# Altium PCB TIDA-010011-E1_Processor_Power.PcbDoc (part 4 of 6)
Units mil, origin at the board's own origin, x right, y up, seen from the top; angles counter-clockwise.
Board outline 4921.26 x 4921.26 mil, 4 copper layers (Top Layer, Gnd layer, Gnd/Pwr layer, Bottom Layer), stack 62.634 mil thick; 631 components, 254 nets, 1751 pads, 757 vias.
Unrouted connection lines stored in the file: 1.
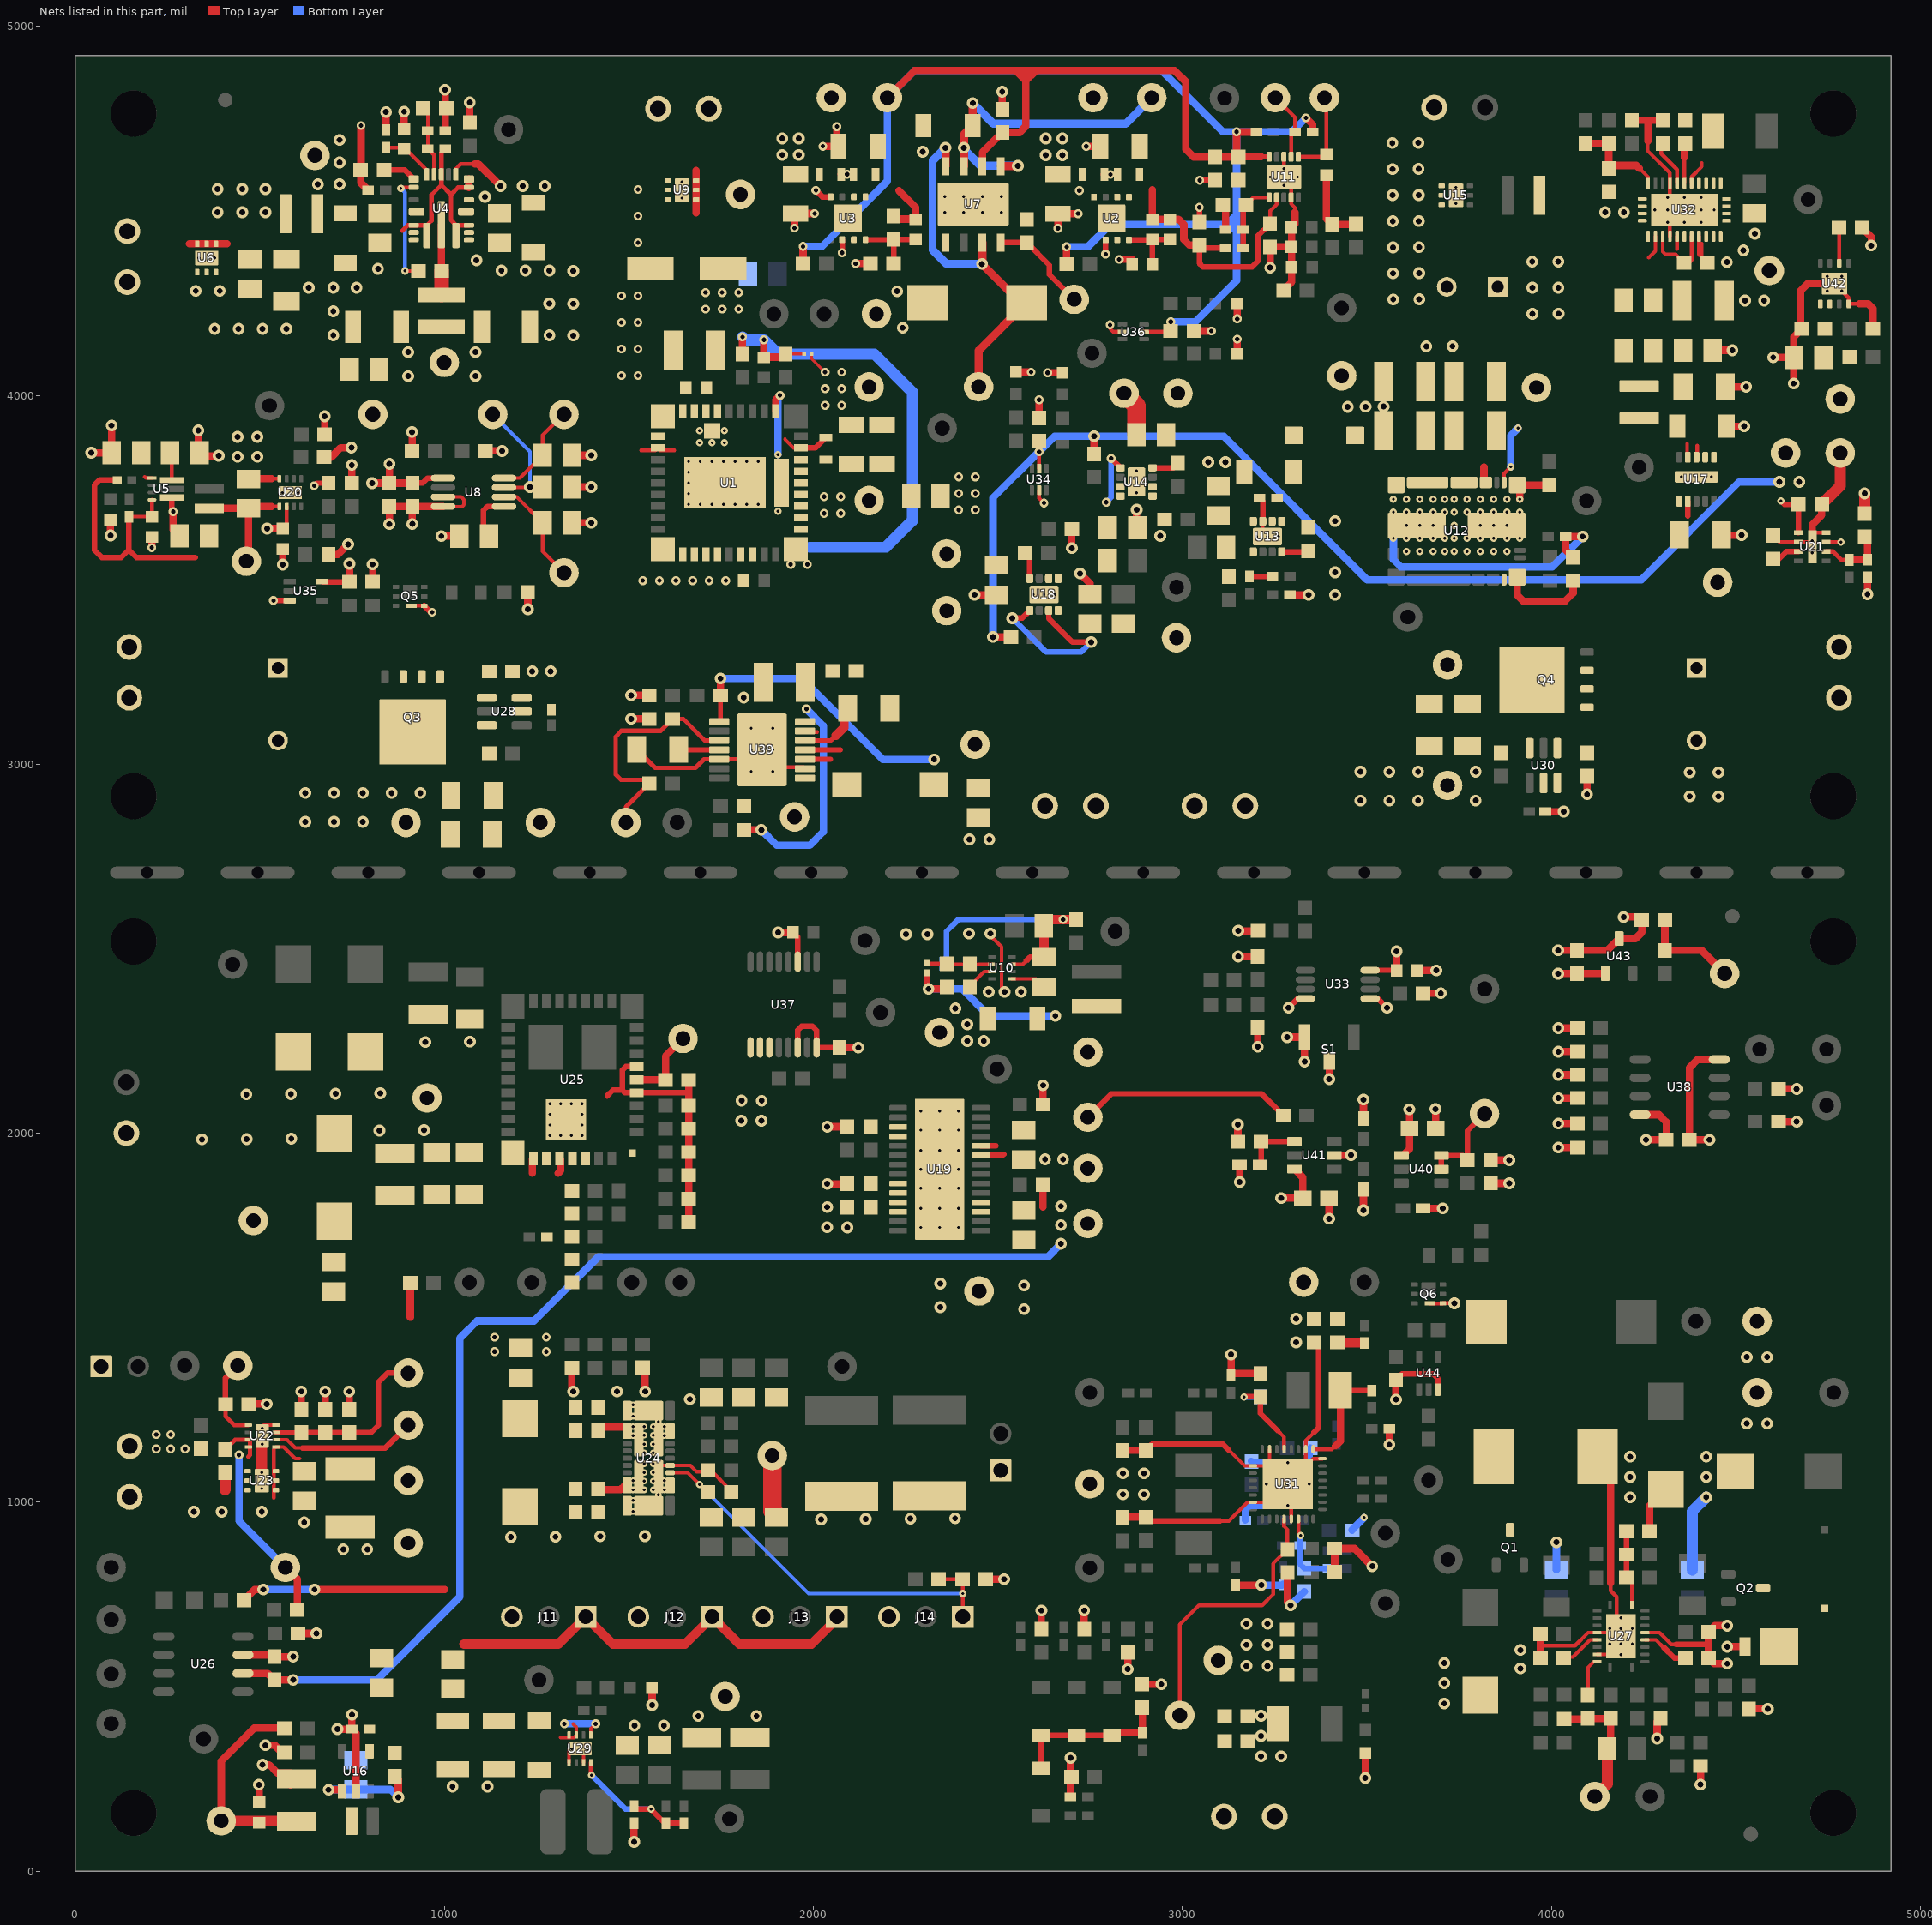
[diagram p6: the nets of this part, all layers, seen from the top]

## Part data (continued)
U41: "Low Quiescent Current, Programmable-Delay Supervisory Circuit, DBV0006A (SOT-6)", Alternate Manufacturer="Texas Instruments", Alternate PartNumber=TPS3808G01DBVT, Supplier Part Number 1=296-17188-1-ND
U42: library part CMP-0065176-3, "Low-Noise, High-Bandwidth PSRR, 1A Low-Dropout Linear Regulator, DRB0008A (VSON-8)", Alternate Manufacturer="Texas Instruments", Alternate PartNumber=TPS7A8001ADRBT, Supplier Part Number 1=296-27630-1-ND
U43: library part CMP-0013240-2, "TMP235DBZ, DBZ0003A (SOP-3)", Alternate Manufacturer="Texas Instruments"
U44: library part CMP-0051704-3, "Single Schmitt-Trigger Buffer, DCK0005A, LARGE T&R", F @ Nom Voltage(Max)(Mhz)=150, Generic Part Number=SN74LVC1G17, ICC @ Nom Voltage(Max)(mA)=0.01, Manufacturer="Texas Instruments", Operating Temperature Range(C)="-40 to 125,-40 to 85", Rating=Catalog, tpd @ Nom Voltage(Max)(ns)=11,6.5,5.5,5, Voltage(Nom)(V)=1.8,2.5,3.3,5
ZZ1: library part AssemblyNoteLabel, Alternate Manufacturer=-
ZZ2 ZZ3 ZZ4: library part AssemblyNote, Alternate Manufacturer=-

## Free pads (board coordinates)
  oval 200x32 hole 32 slot 200 at 0 deg unplated mask+10: 0(194,2706.42) 0(494,2706.42) 0(794,2706.42) 0(1094,2706.42) 0(1394,2706.42) 0(1694,2706.42) 0(1994,2706.42) 0(2294,2706.42) 0(2594,2706.42) 0(2894,2706.42) 0(3194,2706.42) 0(3494,2706.42) 0(3794,2706.42) 0(4094,2706.42) 0(4394,2706.42) 0(4694,2706.42)

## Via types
v1: diameter 32, hole 16, Top Layer to Bottom Layer, tented both sides, 400 vias
v2: diameter 19.68, hole 7.87, Top Layer to Bottom Layer, 176 vias
v3: diameter 24, hole 12, Top Layer to Bottom Layer, tented both sides, 112 vias
v4: diameter 20, hole 8, Top Layer to Bottom Layer, tented both sides, 35 vias
v5: diameter 17.72, hole 7.87, Top Layer to Bottom Layer, 30 vias
v6: diameter 19.68, hole 7.87, Top Layer to Bottom Layer, tented both sides, 4 vias

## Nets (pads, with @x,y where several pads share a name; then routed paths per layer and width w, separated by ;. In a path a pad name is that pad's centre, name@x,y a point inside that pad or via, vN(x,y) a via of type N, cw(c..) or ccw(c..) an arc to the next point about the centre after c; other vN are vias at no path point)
1.2V/1A: C183.1 C185.1 L18.2 R174.2 TP104.1 | length 470.8
  Top Layer w15: C183.1@2309,2435.01 2309,2394 v1(2312,2391)
  Top Layer w20: v1(2312,2391) 2355.5,2391 R174.2@2361,2396.5
  Bottom Layer w20: v1(2312,2391) 2403,2391 2476,2318 v1(2656,2318)
1.2V_CPM: C51.1 R25.2 TP13.1 U14.8 | length 74.2
  Top Layer w15: U14.8@2919,3803.5 2975.5,3803.5 R25.2@2988,3816
1.8V: C9.1 C10.1 C11.1 C42.1 C170.1 C174.2 R1.2 R22.2 TP6.1 U2.5 U7.5 U7.7 U11.2 | length 1675.7
  Top Layer w10: C170.1@3238,4465.5 3238,4500 3255.43,4517.43 U11.2@3255.43,4536.35
  Top Layer w15: C42.1@3046,4406.97 C42.1@3046,4406.5 ; R22.2@3117.49,4399.46 3053.04,4399.46 C42.1@3046,4406.5 ; C170.1@3238,4465.5 3204.1,4431.6 3204.1,4363.1 3189,4348 3056,4348 3046,4358 C42.1@3046,4406.5
  Top Layer w20: 2918.87,4556.87 R1.2@2918.87,4477.33 2918.93,4477.39 C9.1@2966.07,4477.39 2989.61,4477.39 3004,4463 3004,4422 3019.03,4406.97 C42.1@3046,4406.97
  Top Layer w22: U7.7@2408,4620.69 v1(2408,4671) 2408,4707.07 C174.2@2431.93,4731 v1(2431.93,4791.93) ; U7.5@2508,4620.69 2553.69,4620.69 v1@2554,4621
  Bottom Layer w22: v1@2408,4667 2453,4622 v1(2554,4622) ; v1(2431.93,4791.93) 2487.86,4736 2846.5,4736 TP6.1@2917.07,4806.57
1.8V_CPM: C59.1 R35.2 TP19.1 U18.8 | length 74.2
  Top Layer w15: R35.2@2574.24,3572.24 2586.74,3559.75 U18.8@2586.74,3503.24
3.3V: C14.1 C15.1 C16.1 C40.1 C41.1 C158.1 C175.1 R5.2 R21.2 R23.2 R139.2 R141.2 TP8.1 U3.5 U7.6 U11.10 U36.5 | length 5154.7
  Top Layer w12: U36.5@2896.13,4171.72 2965.76,4171.72 C158.1@2968.5,4174.46 v3(2968.5,4199.22) ; 3213.11,4646.58 U11.10@3235.75,4646.58
  Top Layer w20: R141.2@1972.01,4357.06 v3(1972.01,4403.49) ; TP8.1@2200.5,4806.56 2273.94,4880 2979,4880 3009,4850 3009,4667 3030.04,4645.96 C40.1@3089.12,4645.96 C41.1@3152.12,4645.96 ; R5.2@2217.5,4485.49 2225.44,4477.55 C14.1@2277.5,4477.55 2277.5,4508.99 2231.5,4554.99 ; U7.6@2458,4620.69 2458,4658.5 C175.1@2512,4712.5 2559.5,4712.5 2576,4729 2576,4880 ; 2552,4880 2552,4877 2576,4853 2600,4877 2600,4880 ; R139.2@2686.5,4356 v3(2686.5,4402.43) ; R21.2@3200.49,4713.46 3147.54,4713.46 v3(3147,4714) 3147,4651.08 C41.1@3152.12,4645.96 ; 3213.11,4646.58 3152.74,4646.58 C41.1@3152.12,4645.96 ; v3(3335,4752) 3352.74,4734.26 R23.2@3352.74,4713.46
  Bottom Layer w20: v3(1972.01,4403.49) 2023.49,4403.49 2200.5,4580.5 TP8.1@2200.5,4806.56 2273.94,4880 2944,4880 3110,4714 v3(3147,4714) ; v3(2686.5,4402.43) 2726.57,4402.43 2744.43,4402.43 2805,4463 3147,4463 ; v3(2968.5,4199.22) 3035.22,4199.22 3147,4311 3147,4463 ; 3124,4463 3124,4467 3147,4490 ; 3128,4463 3147,4444 ; v3(3335,4752) 3297,4714 v3(3147,4714) ; 3147,4463 3147,4490 ; 3147,4490 v3(3147,4714)
3.3V_H: C31.1 C32.1 C147.1 C157.1 R12.2 R13.2 R14.2 R15.2 R112.2 R114.1 R118.1 R135.2 R138.1 TP75.1 U8.1 U20.2 U20.8 U35.5 | length 989.6
  Top Layer w10: 531.34,3773.66 U20.8@552.76,3773.66 ; C147.1@562,3638.56 572.44,3649 U20.2@572.44,3698.86
  Top Layer w15: U35.5@669.29,3494.85 669.88,3494.26 C157.1@742.5,3494.26 ; C32.1@912.5,3762.25 C32.1@913.5,3762.25 ; C32.1@913,3761.76 C32.1@913.5,3762.25 ; U8.1@996.32,3775.65 954.65,3775.65 941.25,3762.25 C32.1@913.5,3762.25
  Top Layer w20: R118.1@463,3779.26 R118.1@469,3773.26 469.4,3773.66 531.34,3773.66 ; v1(519.56,3638.56) C147.1@562,3638.56 ; R112.2@675.5,3894 v1(675.5,3943.24) ; R138.1@686,3568.76 711.76,3568.76 v1(739,3596) ; C157.1@742.5,3494.26 v1(742.5,3543.15) ; R114.1@749,3761.76 v1(749,3811) ; v1(804.24,3761.76) C31.1@851,3761.76 ; v1(851,3814) C31.1@851,3761.76 ; R15.2@912.5,3849.26 v1(912.5,3900.5) ; C32.1@913,3761.76 C31.1@851,3761.76 ; R135.2@1225.5,3466.26 1226,3466.76 v1(1226,3420) ; R14.2@1346,3654.26 v1(1397.74,3654.26) ; R13.2@1346,3751.26 v1(1397.74,3751.26) ; R12.2@1346,3837.26 v1(1397.74,3837.26)
  other v1: 439,3833 493,3833 439,3887 493,3887
3.6I_1P8V: C143.1 R165.1 TP57.1 U19.23 U19.24 | length 684.1
  Top Layer w15: U19.23@2454.2,1940.39 2513.39,1940.39 2516,1943 ; U19.24@2454.2,1965.98 2494.98,1965.98 ; TP57.1@2744,2043 2808,2107 3214.51,2107 R165.1@3273.51,2048
3.6I_3P3V: C144.1 C148.1 C155.2 C160.2 C166.1 C168.2 C189.2 R20.1 R38.1 R127.1 R146.2 R147.2 R148.2 R149.2 R150.2 R160.2 R162.2 R163.2 R164.2 TP60.1 U19.17 U19.18 U26.2 U33.4 U33.8 U38.8 U40.4 U41.6 U43.1 | length 4518.3
  Top Layer w15: v1(3288,2340) 3312.92,2364.92 U33.4@3333.71,2364.92 ; U33.8@3508.9,2441.69 3580.36,2441.69 C155.2@3580.74,2441.31
  Top Layer w20: U26.2@454.09,535.48 521.31,535.48 C148.1@538.81,517.98 v1(589.98,517.98) ; 2622.5,1799.5 R38.1@2622.5,1860 ; R20.1@2622.5,2078 v1(2622.5,2129.5) ; v1(3155.44,1867.44) R164.2@3155.44,1914 ; v1(3268,1824) C168.2@3326.57,1824 3326.57,1879.9 U41.6@3303.87,1902.6 ; v1(3491,1791) R162.2@3491,1847.44 ; R163.2@3491,2039.56 v1(3491,2091.06) ; C155.2@3580.74,2441.31 v1(3580.74,2492.81) ; U40.4@3593.87,1939.4 3597.84,1939.4 3615.57,1957.13 C166.1@3615.57,2013 v1(3615.57,2064.5) ; R160.2@3652.56,1796 v1(3706,1796) ; R127.1@3652.8,2379.31 v1(3700.69,2379.31) ; v1(4018.5,2432.5) C189.2@4070,2432.5 4070.25,2432.76 U43.1@4146.6,2432.76 ; v1(4019,2026) R146.2@4070.5,2026 ; v1(4019,2095) R147.2@4070.5,2095 ; v1(4019,2285) R148.2@4070.5,2285 ; U38.8@4240.72,2050 4292,2050 4311.5,2030.5 C160.2@4311.5,1982 v1(4257,1982) ; R150.2@4615.5,2031 v1(4665,2031) ; R149.2@4615.5,2120 v1(4665,2120)
  Bottom Layer w20: v1(589.98,517.98) 816.98,517.98 1042,743 1042,1444 1089,1491 1243,1491 1417,1665 2636,1665 v1(2671,1700)
  other v1: 2671,1751 2671,1802
5I_3P3V: C63.1 C156.1 R29.2 R36.1 TP77.1 U21.3 U21.5 U34.5 | length 3189.4
  Top Layer w10: U34.5@2612,3801.13 v3(2612,3847.02) 2612,3871.5 2614,3873.5 C156.1@2612,3875.5 ; U21.3@4744.8,3602 v4(4785,3602)
  Top Layer w15: v4(4622,3714) 4631.8,3704.2 C63.1@4669.91,3704.2 4670,3704.11 U21.5@4670,3627.59
  Top Layer w20: v1(2487,3345) R36.1@2535.5,3345 ; R29.2@2761,3841 v1(2761,3889)
  Bottom Layer w20: v1(2487,3345) 2487,3722.02 v3(2612,3847.02) 2653.98,3889 v1(2761,3889) 3112,3889 3501,3500 4244,3500 4509,3765 v1(4618,3765)
  other v1: 4672,3765
5V: C4.1 C5.1 C6.1 R177.2 TP2.1 U1.13 U1.14 U1.15 U1.16 U1.17 U1.18 U1.22 U1.43 | length 210.6
  Top Layer w20: U1.22@1898,3956.57 1898,3988 v3(1909.67,3999.67)
  Bottom Layer w20: v2(1903.9,3839.44) 1903.9,3993.9 v3(1909.67,3999.67)
  other v2: 1903.9,3685.9
  other v3: 2029,3680 2074,3680 2029,3725 2074,3725
5V_EFUSE_OUT: C65.1 C66.1 J11.1 J12.1 J13.1 R56.1 R120.2 R180.2 R181.1 R182.2 TP23.1 U22.5 U23.4 U23.5 U23.6 | length 2036.6
  Top Layer w10: 537.39,1011.93 537.39,1143.19 537.25,1143.32 U22.5@543.4,1149.47 564.12,1149.47 595.59,1118 607,1118
  Top Layer w20: R120.2@456.5,734 485.5,763 v1(509,763) ; v1@648,761 v1(648,763) 1001,763 ; 907.5,1501.5 R56.1@907.5,1594
  Top Layer w25: 1053,615 1308.81,615 J11.1@1382.73,688.92 1456.65,615 1651.81,615 J12.1@1725.73,688.92 1799.65,615 1994.81,615 J13.1@2068.73,688.92
  Bottom Layer w20: v1(509,763) v1(648,763)
5V_H: C24.1 C25.1 C30.2 L2.2 R10.1 R176.2 RB1.2 RES1.1 TP35.1 | length 214.1
  Top Layer w20: RB1.2@841.74,4718.72 v1(841.74,4767.74) ; R10.1@1002.36,4717.1 v1@1002.36,4828 ; RES1.1@1068.74,4739.6 v1(1068.74,4793.74)
  other v1: 901.52,4052 1084,4052 901.52,4117 1084,4117 1002,4828
12VOUT: C48.1 C49.1 L5.2 R19.2 R32.2 TP15.1 U12.6 U12.7 U12.8@3635.52,3647.64 | length 724
  Top Layer w20: R32.2@4059.2,3560.09 4038.95,3580.34 R19.2@4038.95,3617.09 v1(4085.09,3617.09)
  Bottom Layer w20: v2(3572.25,3612.2) 3572.25,3554.75 3592,3535 4003,3535 v1(4085.09,3617.09)
  other v1: 3448.38,3968.62 3497,3969 3545.62,3969.38
  other v2: 3608.08,3612.2 3643.9,3612.2 3679.73,3612.2 3711.22,3612.2 3608.08,3647.64 3643.9,3647.64 3679.73,3647.64 3572.25,3683.07 3608.08,3683.07 3643.9,3683.07 3679.73,3683.07 3711.22,3683.07 3572.25,3718.5 3608.08,3718.5 3643.9,3718.5 3679.73,3718.5 3711.22,3718.5
24V_S: C45.1 C46.1 C47.1 L4.2 R166.2 R167.2 TP14.1 U12.2 U12.4 | length 206.5
  Top Layer w6: v4@3884,3800 v4(3890,3806)
  Top Layer w10: U12.2@3871.66,3763.98 3871.66,3787.66 v4@3884,3800
  Top Layer w20: 3817.5,3805.5 3817.5,3768.92 U12.4@3822.45,3763.98
  Bottom Layer w20: v4(3890,3806) 3890,3891 v4(3910,3911)
  other v1: 3949,4221 4019.62,4221.38 3948.62,4291.62 4019.24,4292 3948.24,4362.24 4018.86,4362.62
AGND: C111.2 NT1.1 R3.1 R4.1 R18.1 U1.1 U1.2 U1.3 U1.4 U1.5 U1.7 U1.8 U1.11 U1.12 | length 1384.3
  Top Layer w8: R18.1@1924.42,4111.67 NT1.1@1974.67,4111.67
  Top Layer w20: C111.2@1808.01,4111.27 v3(1808.01,4158.32) ; v3(1866.01,4150.38) R4.1@1866.01,4103.33 1916.08,4103.33 R18.1@1924.01,4111.27
  Bottom Layer w30: v3(1808.01,4158.32) 1815.95,4150.38 v3(1866.01,4150.38) 1904.4,4112 2165,4112 2268,4009 2268,3660 2196,3588 1990,3588
  other v3: 1537.67,3497.67 1582.67,3497.67 1627.67,3497.67 1672.67,3497.67 1717.67,3497.67 1762.67,3497.67 1938.67,3541.67 1983.67,3541.67
DDR_VREF: C43.1 TP11.1 U11.6 | length 236.8
  Top Layer w10: U11.6@3314.49,4646.58 3388.61,4646.58 3390.12,4648.09 C43.1@3390.12,4652.02 3390.12,4801.2 TP11.1@3384.86,4806.46
DDR_VTT_EN: R23.1 TP76.1 U11.7 | length 186.4
  Top Layer w10: TP76.1@3267.29,4791.29 3305.49,4753.09 R23.1@3305.49,4713.46 3294.8,4702.77 U11.7@3294.8,4646.58
  Top Layer w12: TP76.1@3252.12,4806.46 TP76.1@3267.29,4791.29
DV/DT: C68.1 TP26.1 U22.1 | length 223.4
  Top Layer w12: C68.1@406.5,1266 406.5,1232.5 430.47,1208.53 U22.1@468.6,1208.53
  Top Layer w15: C68.1@406.5,1266 406.5,1336.5 TP26.1@440,1370
FLAG1: R12.1 TP72.1 U8.8 | length 266.6
  Top Layer w10: U8.8@1161.68,3775.65 1204.39,3775.65 R12.1@1266,3837.26 1266,3892 TP72.1@1324,3950
FLAG2: R13.1 TP73.1 U8.7 | length 343.7
  Top Layer w10: U8.7@1161.68,3750.06 1264.8,3750.06 R13.1@1266,3751.26
  Bottom Layer w10: TP73.1@1131,3948.26 1232,3847.26 v1(1232,3751.26)
FLAG3: R14.1 TP74.1 U8.6 | length 292.7
  Top Layer w10: U8.6@1161.68,3724.46 1195.8,3724.46 R14.1@1266,3654.26 1266,3577 TP74.1@1324,3519
FLT: TP25.1 U22.6 | length 393.5
  Top Layer w10: U22.6@543.4,1169.16 573.28,1169.16 595.43,1147 615.57,1147
  Top Layer w15: 615.57,1147 840,1147 TP25.1@902,1209
GND: C1.2 C2.2 C3.1 C4.2 C5.2 C6.2 C7.2 C8.2 C10.2 C11.2 C12.2 C13.2 C15.2 C16.2 C18.2 C19.2 C20.2 C21.2 C22.2 C23.2 C24.2 C25.2 C26.2 C27.2 C28.2 C29.2 C31.2 C32.2 C33.2 C34.2 C35.2 C36.2 C37.2 C38.2 C39.2 C40.2 C41.2 C42.2 C43.2 C44.2 C45.2 C46.2 C47.2 C48.2 C49.2 C50.2 C51.2 C52.2 C53.2 C54.2 C55.1 C56.2 C57.2 C58.2 C59.2 C60.2 C61.2 C62.2 C63.2 C64.2 C110.2 C127.2 C128.2 C129.2 C130.2 C139.2 C140.2 C141.2 C142.2 C147.2 C150.2 C151.2 C152.1 C153.2 C156.2 C157.2 C158.2 C161.2 C163.2 C164.1 C165.1 C170.2 C171.2 C172.2 C173.2 C174.1 C175.2 C176.2 C182.2 CVCC1.2 D3.2 D4.2 D6.2 D7.2 D10.2 D16.2 J1.2 J2.2 J3.2 J4.1 J18.2 J19.2 J20.1 NT1.2 Q5.4 Q5.7 R2.1 R6.1 R9.1 R11.1 R16.1 R17.2 R24.1 R30.1 R31.1 R33.1 R34.1 R37.1 R40.1 R116.1 R117.1 R123.1 R124.1 R155.1 R159.1 R169.1 TP4.1 TP7.1 TP9.1 TP17.1 TP21.1 TP43.1 TP69.1 TP78.1 TP93.1 TP96.1 TP101.1 U1.19 U1.29 U1.30 U1.31 U1.32 U1.33 U1.41 U2.3 U2.6 U2.9 U3.3 U3.6 U3.9 U4.5 U4.6 U4.7 U4.8 U4.10 U4.11 U4.12 U4.13 U4.16 U4.17 U4.20 U5.5 U6.1 U6.2 U6.3 U6.7@355.41,4372.39 U7.1 U7.9@2433,4517.35 U8.3 U8.4 U9.1 U9.2 U9.3 U9.7@1644.05,4556.26 U11.4 U11.8 U11.11@3275.12,4591.46 U12.1 U12.5 U12.14 U12.15 U12.18@3851.89,3647.64 U13.3 U13.9 U14.5 U14.6 U14.9 U15.1 U15.2 U15.3 U15.7@3741.71,4542.09 U17.1 U17.2 U17.11@4393.62,3779.11 U18.5 U18.6 U18.9 U20.9@582.28,3736.26 U21.4 U21.6 U21.9 U28.2 U28.3 U30.2 U30.3 U32.8 U32.12 U32.13 U32.14 U32.15 U32.16 U32.17 U32.19 U32.23 U32.24 U32.25 U32.26 U32.27 U32.28 U32.29 U32.30 U32.31 U34.2 U35.3 U36.2 U39.5 U39.8 U39.9 U39.15@1861,3039 U42.4 U42.9 | length 7675
  Top Layer w8: NT1.2@1994.67,4111.67 1994.67,4099.67 v3(2031.67,4062.67)
  Top Layer w10: Q5.7@910.74,3429.67 Q5.4@945.39,3429.67 ; U8.4@996.32,3698.87 997.2,3698 1048,3698 1053,3703 1053,3717 1045.54,3724.46 U8.3@996.32,3724.46 ; 1532.67,3850.67 1571.63,3850.67 U1.33@1578.12,3857.16 1584.77,3850.5 1623.5,3850.5 ; U39.15@1861,3039 1908.15,2991.85 1973.11,2991.85 U39.9@1977.14,2987.82 ; 1923.19,3880.67 1946.7,3857.16 U1.19@1965.91,3857.16 ; U34.2@2612,3742.87 2612,3721 v3(2625,3708) ; v3(2804,4191) 2804,4181 2812.2,4172.8 2836.79,4172.8 U36.2@2837.87,4171.72 ; U13.9@3217.94,3629.8 U13.3@3217.94,3658.34 ; U11.8@3275.12,4646.58 v2(3275.12,4614.1) U11.11@3275.12,4591.46 3294.8,4571.78 U11.4@3294.8,4536.35 3294.8,4519.2 3305,4509 3305,4496 ; 4261.6,4689 4261.6,4662.4 4321.54,4602.46 U32.8@4321.54,4574.69 4321.54,4542.21 v2(4360.91,4502.84) 4321.54,4463.47 U32.19@4321.54,4430.99 ; 4264,4373 4282.17,4391.17 U32.17@4282.17,4430.99 ; U32.23@4400.28,4430.99 4400.28,4381.95 C151.2@4408,4374.24 ; 4408,4411.22 C151.2@4408,4374.24 ; C151.2@4423.24,4359 C151.2@4408,4374.24 ; C62.2@4601.4,3619.7 4619.1,3602 U21.6@4670,3602 4704.06,3602 v2(4707.4,3605.35) ; U21.9@4707.4,3627.59 U21.4@4744.8,3627.59 ; U42.9@4767.55,4302.92 4805.94,4264.53 U42.4@4805.94,4247.8 4835.46,4247.8
  Top Layer w12: 886,4446 900.84,4460.84 U4.5@916.94,4460.84 952.16,4460.84 965,4473.68 965,4543.52 991.74,4570.26 ; U4.8@952.37,4433.28 U4.8@953,4432.65 ; R9.1@1002.36,4668.1 991.74,4657.48 U4.20@991.74,4598.64 991.74,4570.26 ; U4.10@1031.11,4433.28 U4.10@1031.11,4460.84 ; U4.13@1066.54,4460.84 U4.10@1031.11,4460.84 ; U4.16@1066.54,4563.2 1037.2,4563.2 1018,4544 ; C164.1@1520.91,3040 1571.03,2989.88 1680.37,2989.88 1703.89,3013.41 1704.41,3013.41 ; 1702.52,3011.52 1704.41,3013.41 ; U39.15@1861,3039 1835.41,3013.41 U39.5@1744.86,3013.41 1704.41,3013.41 ; 991.74,4570.26 1018,4544 ; 1018,4544 1018,4475 1031.11,4461.89 U4.10@1031.11,4460.84
  Top Layer w15: U5.5@260.72,3722.64 260.72,3688.48 v3(264.6,3684.6) ; v3(536.67,3443.67) U35.3@580.71,3443.67 ; v3(647,3755) 653.76,3761.76 R117.1@686,3761.76 ; Q5.4@945.39,3429.67 963,3412.06 964.94,3414 v3(967,3411.94) ; U1.19@1965.91,3857.16 2005.4,3857.16 C4.2@2034.01,3885.77 ; C42.2@3046,4465.46 C42.2@3046,4469.5 v3(3046,4509.61) ; v3(3047.03,4582.97) C40.2@3089.12,4582.97 ; C53.2@3209.12,3721 3217.94,3712.17 U13.3@3217.94,3658.34 ; U13.9@3217.94,3629.8 v2(3230.74,3617)
  Top Layer w20: v1(43,3844) C110.2@98,3844 v1(98,3918) ; v1(95,3620) R11.1@95,3662.7 ; v3(207,3587.28) C29.2@207,3615.7 ; v3(264.6,3684.6) 264.6,3636.4 C28.2@282,3619 ; v1(333,3905) 333,3836.66 333.66,3836 v1(388,3836) ; v1(562,3541) C147.2@562,3583.44 ; R116.1@674.5,3832.26 693.26,3832.26 719,3858 v1(748,3858) ; v3(774,4731) 774,4611.86 CVCC1.2@773.24,4611.1 773.24,4575.98 R17.2@793.12,4556.1 ; C157.2@805.5,3494.26 v1(805.5,3541.5) ; v1(850.89,3650.89) C31.2@850.89,3698.65 ; C31.2@851,3698.76 C32.2@913,3698.76 ; C26.2@890.74,4718.72 C26.2@890.74,4722.66 v1(890.74,4768.74) ; v1(913,3651) C32.2@913,3698.76 ; v1(991.74,3618.26) C33.2@1041,3618.26 ; U8.4@996.32,3698.87 913.11,3698.87 C32.2@913,3698.76 ; U4.16@1066.54,4563.2 U4.17@1066.54,4585.84 ; R16.1@1111.5,3849.26 v1(1156.26,3849.26) ; v1(1506,3123) C165.1@1555.5,3123 ; v1(1506,3187) R155.1@1555.5,3187 ; v3(1948.81,4453.25) 1948.81,4492.84 C12.2@1951.5,4492.84 v3(2003.22,4492.84) ; v3(2025.55,4674.99) 2063.66,4674.99 v3(2063.66,4728.4) ; C13.2@2074.81,4598.99 C13.2@2075.5,4598.99 v3(2091.07,4598.99) ; v3(2114.5,4356.99) R6.1@2154.51,4356.99 ; v1(2436.76,3459.24) C59.2@2496.74,3459.24 ; C175.2@2512,4775.5 v1(2512,4823) ; D6.2@2549.54,4062.94 v3(2590.13,4062.94) ; C156.2@2612,3938.5 v3(2612,3988) ; v3(2634.94,4060.94) D7.2@2675.54,4060.94 ; v3(2663.07,4452.83) C7.2@2663.07,4492.42 v3(2717.48,4492.42) ; v1(2700.5,3585.5) R37.1@2700.5,3637 ; v1(2723,3517) 2749.74,3490.26 C61.2@2749.74,3461.24 ; v3(2739.81,4674.57) C10.2@2777.92,4674.57 ; C8.2@2789.07,4598.57 v3(2805.33,4598.57) ; v3(2828.81,4368.57) R2.1@2863.51,4368.57 ; v1(2876,3690) 2876,3642.5 C52.2@2878,3640.5 ; C158.2@3031.5,4174.46 v3(3078.74,4174.46) ; C44.2@3109.5,4516 3117.49,4508.01 R24.1@3117.49,4449.46 ; D10.2@3148.53,4111.72 v3(3148.53,4152.39) ; v3(3148.53,4207.24) D16.2@3148.53,4247.91 ; v1(3238,4346) C170.2@3238,4402.5 3238.29,4402.8 C38.2@3295.64,4402.8 ; C34.2@3274.5,4285 3296.64,4307.14 C37.2@3296.64,4347.8 3296.64,4453.8 C39.2@3295.64,4454.8 3305,4464.15 3305,4496 ; R31.1@3291.36,3459 v1(3342,3459) ; C43.2@3390.12,4596.91 3390.12,4479.38 C36.2@3406,4463.5 3469,4463.5 C35.2@3470,4464.5 ; U12.15@3907.68,3507.09 3907.68,3458.32 3925,3441 4036,3441 4059.2,3464.2 R33.1@4059.2,3497.09 ; U12.1@3907.68,3757.09 U12.1@3908.18,3756.59 ; v2(3914.96,3718.5) 3914.96,3749.8 U12.1@3908.18,3756.59 ; D4.2@3983.65,2871.43 v1(4033.9,2871.43) ; R34.1@3993.71,3756.59 U12.1@3908.18,3756.59 ; v1(4097,2918.53) C140.2@4097,2967.93 ; R123.1@4224.74,4745.5 4262,4745.5 ; 4261.6,4689 4261.6,4745.1 4262,4745.5 ; C152.1@4298,4745.5 4262,4745.5 ; C56.2@4437.38,4122.26 4437.64,4122 v1(4491,4122) ; C60.2@4461.09,3622 4462.09,3621 v1(4516,3621) ; C57.2@4471.46,4023.26 4471.72,4023 v1(4528,4023) ; C58.2@4475.31,3916.26 4475.57,3916 v1(4523,3916) ; v1(4601.2,4102.8) C172.2@4656.94,4102.8 ; v1(4656.94,4032.06) C172.2@4656.94,4102.8 ; U21.9@4707.4,3589.2 v2(4707.4,3605.35) 4707.4,3627.59 4707.4,3649.4 4732.9,3674.9 C63.2@4732.9,3704.2 ; U42.9@4767.55,4302.92 4694.92,4302.92 4676,4284 4676,4182.24 C171.2@4678.44,4179.8 4656.94,4158.3 C172.2@4656.94,4102.8 ; 4835.46,4247.8 4859.2,4247.8 4871.5,4235.5 R169.1@4871.5,4180 ; C173.2@4842.5,4454 4867,4429.5 v1(4867,4406) ; v1(4857,3460.98) R40.1@4857,3506.76
  Top Layer w30: C63.2@4732.9,3704.2 4783,3754.31 TP78.1@4783,3843.82 ; C64.2@4849,3679.5 v1(4849,3734)
  Top Layer w50: TP17.1@2842,4005.5 2876,3971.5 C51.2@2876,3893.5
  other v1: 2423,2796 2477,2796 623,2844 701,2844 779,2844 3483,2901.53 3561,2901.53 3639,2901.53 3795,2901.53 4375,2913 4453,2913 623,2922 701,2922 779,2922 857,2922 935,2922 4375,2978 4453,2978 3483,2979.53 3561,2979.53 3639,2979.53 3795,2979.53 1811,3181 1238,3252 1288,3252 3414,3459 3414,3520 2940,3619 3414,3659 3070,3819 3117,3819 3661.38,4132.62 3732,4133 1349.48,4162 699,4163 1284.48,4163 377,4180 442,4180 507,4180 572,4180 2242,4183 699,4228 1349,4248 1284,4249 4525,4257 4577,4257 3571.76,4260 3642.38,4260.38 2227,4282 326,4283 391,4283 632,4292 699,4292 762,4292 3571.38,4330.62 3642,4331 1349.48,4337 1154.48,4338 1219.48,4338 1284.48,4338 820,4343 4476,4361 1087,4366 4521,4393 3571,4401.24 3641.62,4401.62 4552,4438 3570.62,4471.86 3641.24,4472.24 4146,4496 4197,4496 3570.24,4542.47 3640.86,4542.86 3569.86,4613.09 3640.47,4613.47 2296,4660 3569.47,4683.71 3640.09,4684.09
  other v2: 1831.47,2979.94 1890.53,2979.94 1831.47,3039 1890.53,3039 1831.47,3098.06 1890.53,3098.06 2595.6,3459.94 2625.13,3459.94 2654.65,3459.94 4707.4,3573.06 3608.08,3576.77 3643.9,3576.77 3679.73,3576.77 3711.22,3576.77 3736.82,3576.77 3771.85,3576.77 3807.68,3576.77 3843.51,3576.77 3879.34,3576.77 3736.82,3612.2 3771.85,3612.2 3807.68,3612.2 3843.51,3612.2 3879.34,3612.2 3914.96,3612.2 3201.21,3617 3260.27,3617 3736.82,3647.64 3807.68,3647.64 3843.51,3647.64 3879.34,3647.64 3736.82,3683.07 3771.85,3683.07 3807.68,3683.07 3843.51,3683.07 3879.34,3683.07 3914.96,3683.07 1661.78,3704.6 1693.27,3704.6 1724.77,3704.6 1756.27,3704.6 1787.76,3704.6 1819.26,3704.6 1850.75,3704.6 3736.82,3718.5 3771.85,3718.5 3807.68,3718.5 3843.51,3718.5 3879.34,3718.5 1661.78,3733.53 2875.69,3735.59 560.63,3736.26 603.94,3736.26 1661.78,3762.67 2875.69,3765.12 4353.07,3779.11 4393.62,3779.11 4434.17,3779.11 1661.78,3791.8 2875.69,3794.65 1661.78,3820.74 1693.27,3820.74 1724.77,3820.74 1756.27,3820.74 1787.76,3820.74 1819.26,3820.74 1850.75,3820.74 4747.87,4283.23 4787.24,4283.23 4747.87,4322.6 4787.24,4322.6 333.76,4372.39 377.06,4372.39 4315.24,4469.38 4360.91,4469.38 4406.58,4469.38 2407.41,4495.69 2458.59,4495.69 4280.2,4502.84 4315.24,4502.84 4406.58,4502.84 4441.62,4502.84 3741.71,4520.43 1644.05,4534.61 4315.24,4536.31 4360.91,4536.31 4406.58,4536.31 2407.41,4539 2458.59,4539 3741.71,4563.74 3275.12,4568.83 1644.05,4577.91 3237.72,4591.46 3312.52,4591.46
  other v3: 2031.67,3972.67 2076.67,3972.67 2031.67,4017.67 2076.67,4017.67 1479.67,4053.67 1524.67,4053.67 2076.67,4062.67 1479.67,4125.67 1524.67,4125.67 1479.67,4197.67 1524.67,4197.67 1479.67,4269.67 1524.67,4269.67 1524.67,4413.67 1524.67,4485.67 1524.67,4557.67
  other v6: 2356.23,4495.69 2509.77,4495.69 2356.23,4539 2509.77,4539
GND_5V: C65.2 C66.2 C67.2 C68.2 C69.2 C70.2 C71.2 C72.1 C73.2 C74.2 C75.2 C76.2 C77.2 C78.2 C79.2 C80.2 C81.2 C82.2 C83.2 C84.2 C85.2 C86.2 C87.2 C88.2 C89.2 C90.2 C91.2 C92.2 C93.2 C94.2 C95.2 C96.2 C97.2 C98.2 C99.2 C100.1 C101.2 C102.2 C103.2 C104.2 C105.2 C106.2 C107.2 C108.2 C109.1 C112.2 C113.2 C114.2 C115.2 C116.2 C117.2 C118.2 C119.2 C120.2 C121.2 C122.2 C123.2 C124.2 C126.2 C131.2 C132.2 C133.2 C134.2 C135.2 C136.2 C137.2 C143.2 C144.2 C145.2 C146.2 C148.2 C155.1 C159.2 C160.1 C166.2 C167.2 C168.1 C169.2 C177.2 C178.2 C179.2 C180.2 C181.2 C184.2 C185.2 C186.2 C187.2 C188.2 C189.1 C190.1 C191.1 C192.2 C193.2 D1.2 D2.2 D8.2 D15.1 J5.2 J6.1 J10.1 J11.3 J12.3 J13.3 J14.3 J16.2 J21.1 Q6.4 Q6.7 R42.1 R43.1 R44.1 R49.1 R50.1 R51.1 R53.1 R54.1 R57.1 R58.1 R59.1 R60.1 R61.1 R62.1 R63.1 R64.1 R65.1 R66.1 R67.1 R69.1 R74.2 R79.1 R85.1 R86.1 R92.1 R97.1 R100.1 R103.2 R106.2 R108.1 R111.1 R121.1 R126.1 R129.1 R131.1 R145.2 R151.2 R152.2 R153.2 R161.2 R175.1 R185.1 S1.2 S1.3 TP37.1 TP39.1 TP42.1 TP44.1 TP45.1 TP46.1 TP53.1 TP56.1 TP58.1 TP59.1 TP61.1 TP86.1 TP106.1 U10.3 U10.5 U16.2 U19.3 U19.4 U19.9 U19.10 U19.29@2342,1902 U22.8 U22.9@506,1179 U23.1 U23.2 U23.3 U23.7@505,1058.28 U24.2@1553.73,1247.86 U24.3 U24.11@1495.66,989.98 U24.12@1553.73,989.98 U24.14 U24.16 U24.20@1611.8,1192.74 U24.21@1580.31,1169.12 U24.22@1580.31,1068.72 U25.1 U25.5 U25.7 U25.29 U25.33 U25.34 U25.37 U26.3 U27.6 U27.15 U27.18 U27.21@4189.04,636.16 U29.1 U29.3 U29.9@1367.16,331.4 U31.2 U31.7 U31.13 U31.24 U31.26 U31.31 U31.33 U33.5 U37.6 U37.8 U37.11 U38.4 U41.2 U43.3 U44.3 | length 10598.9
  Top Layer w10: U22.9@506,1179 v2(506,1200.65) 506,1205.06 509.47,1208.53 U22.8@543.4,1208.53 ; U29.1@1337.63,294 1337.63,331.4 v2(1345.5,331.4) U29.9@1367.16,331.4 1377,321.56 U29.3@1377,294 ; U24.22@1589.66,1099.24 U24.16@1611.8,1099.24 1666.76,1099.24 1683.08,1082.92 1725.34,1082.92 1745.11,1063.15 1745.11,1063.04 1752.55,1055.6 1752.66,1055.6 C100.1@1781.34,1026.92 ; R175.1@2424,2396.5 2424,2399 2463.16,2438.16 U10.3@2484.43,2438.16 ; v1@2480,2535 2510,2505 2510,2391 v1(2518,2383) ; U10.5@2537.57,2418.47 2603.53,2418.47 C184.2@2625,2397 ; 3102,949 3126,949 3176.63,999.63 U31.7@3191,999.63 3236.28,999.63 v2(3285.49,1048.84) ; 3126,1141 3168.94,1098.06 U31.2@3191,1098.06 U31.33@3236.28,1098.06 ; U31.31@3236.28,1143.33 U31.33@3236.28,1098.06 ; U31.13@3295.33,954.35 3295.33,1039 v2(3285.49,1048.84) ; 3357,1189 3334.7,1166.7 U31.26@3334.7,1143.33 U31.33@3334.7,1098.06 ; U31.24@3379.98,1117.74 3354.39,1117.74 U31.33@3334.7,1098.06 ; Q6.7@3671.74,1538.41 Q6.4@3706.39,1538.41 3706.98,1539 v1(3737,1539) ; C117.2@3970.5,642 3970.5,577.5 C119.2@3971.01,577 ; 3971.01,610.6 4064.34,610.6 4099.74,646 U27.15@4124.08,646 4179.19,646 U27.21@4189.04,636.16 4189.04,681.43 4177.21,693.26 4177.21,743.36 4161,759.57 4161,780 ; U27.18@4124.08,586.94 4165.94,586.94 U27.21@4189.04,610.04 ; U27.6@4254,646 4293.57,646 4325.47,614.1 4338.1,614.1 ; U31.33@3236.28,1098.06 v2(3285.49,1048.84) ; v2(3285.49,1048.84) U31.33@3334.7,1098.06
  Top Layer w15: 1441,2101 1457,2117 1482,2117 ; U25.7@1521.38,2180.36 1491.36,2180.36 1482,2171 1482,2117 ; 1662.22,2109.49 U25.5@1521.38,2109.49 1489.51,2109.49 1482,2117 ; C159.2@1944.91,2544.78 1957.82,2531.86 U37.11@1957.82,2464.76 ; U37.6@1957.82,2232.47 1957.82,2279.14 1968.47,2289.78 1997.47,2289.78 2009,2278.24 U37.8@2009,2232.47 2070.73,2232.47 R145.2@2071.23,2231.97 ; C80.2@2900.42,1140.35 2917.08,1157 3110,1157 3126,1141 ; C70.2@2900.49,959.34 2910.83,949 3102,949 ; 3357,1189 3370,1202 3370,1420.1 C74.2@3356.99,1433.11 ; U33.5@3508.9,2364.92 3529.68,2364.92 v1(3554.61,2340) ; C193.2@3579,1330.5 3596.5,1348 3680,1348 3693.18,1334.82 U44.3@3693.18,1305 ; U27.21@4189.04,636.16 U27.21@4197,628.19 ; 4338.1,614.1 4425.6,614.1 4426.5,615
  Top Layer w20: U26.3@454.09,585.48 534.31,585.48 C148.2@538.81,580.98 v1(589.98,580.98) ; C68.2@469.5,1266 v1(518,1266) ; v1(497,234) 497.61,233.39 C191.1@497.61,186.14 ; v1(507,288) 525,288 547,266 582.58,266 C188.2@598.97,249.61 C188.2@582.58,233.22 ; v1(515,341) 540,341 559.47,321.53 R185.1@565.47,321.53 ; R121.1@603.5,644 v1(653,644) ; R42.1@612,1251.5 v1(612,1300) ; R43.1@677,1251.5 v1(677,1300) ; v1(710.22,384.53) C186.2@749.35,384.53 ; R44.1@742,1251.5 v1(742,1300) ; v1(749.35,423.65) C186.2@749.35,384.53 ; U16.2@759.97,220.33 759.97,373.9 C186.2@749.35,384.53 ; R51.1@1345.24,1364.86 1345.24,1303.76 v1(1349,1300) ; v1(1514,79.38) R69.1@1514,123 ; R50.1@1537.23,1364.92 1544,1358.15 v1(1544,1300) ; D8.2@1562.53,496 1563,495.53 v1(1563,450) ; R62.1@1662.22,1759.51 R63.1@1662.22,1822.51 R64.1@1662.22,1885.51 R65.1@1662.22,1948.51 R66.1@1662.22,2011.51 R67.1@1662.22,2074.05 1662.22,2109.49 C109.1@1662.22,2144.05 ; v1(1904.47,2543.78) 1943.91,2543.78 C159.2@1944.91,2544.78 ; v1(2037.5,1862.5) C145.2@2092,1862.5 ; v1(2037.5,2017.5) C112.2@2092,2017.5 ; R145.2@2071.23,2231.97 v1(2121.66,2231.97) ; R53.1@2467.23,790.92 v1(2517.08,790.92) ; C85.2@2618,655.5 v1(2618,706) ; R85.1@2696.59,201 2697,201.41 v1(2697,307) ; C83.2@2734,655.5 v1(2734,706) ; C81.2@2837.42,1140.35 C80.2@2900.42,1140.35 ; C71.2@2837.49,958.34 2838.49,959.34 C70.2@2900.49,959.34 ; v1(2852,547) C79.2@2852,592.5 ; C76.2@2891.53,506.12 v1(2942.88,506.12) ; v1(3132,1400) R92.1@3132,1343.62 3136.87,1348.5 C72.1@3212,1348.5 ; R79.1@3144.49,774.98 v1(3214,774.98) ; C169.2@3150.5,1977 v1(3150.5,2023.5) ; v1(3151.2,2478.8) R129.1@3204.3,2478.8 ; v1(3151.7,2548.31) R131.1@3204.81,2548.31 ; v1(3204.37,2234.37) R126.1@3204.37,2285.81 ; v1(3284,2260.31) S1.2@3331.37,2260.31 v1(3331.37,2194.37) ; C192.2@3285,809.01 3285,728.14 v1(3293.14,720) ; C168.1@3397.43,1824 3397.43,1768.57 v1(3398,1768) ; v1(3398.3,2146.7) S1.3@3398.3,2195.35 ; U41.2@3412.13,1940 3456,1940 v1(3457,1941) ; C73.2@3412.99,811 C86.2@3412.99,874.02 3466.98,874.02 v1(3515,826) ; v1(3496,252) D15.1@3496,320.5 ; v1(3561.24,1155.76) R86.1@3561.24,1198.62 ; v1(3579,1278) C193.2@3579,1330.5 ; C155.1@3635.86,2441.31 v1(3688.31,2441.31) ; C166.2@3686.43,2013 v1(3686.43,2065.57) ; R161.2@3835.5,1864 v1(3886,1864) ; C167.2@3835.5,1927 v1(3886,1927) ; C117.2@3970.5,642 3971.01,641.5 3971.01,610.6 C119.2@3971.01,577 ; v1(4018.5,2495.5) C189.1@4070,2495.5 4152.25,2495.5 U43.3@4184,2527.24 4228.24,2527.24 4245.5,2544.5 C190.1@4245.5,2578 4237.5,2586 v1(4196,2586) ; v1(4019,1961) R151.2@4070.5,1961 ; v1(4019,2158) R152.2@4070.5,2158 ; v1(4019,2221) R153.2@4070.5,2221 ; R74.2@4034.5,412 4097.5,412 C123.2@4099,413.5 C118.2@4161,413.5 4161,340 C126.2@4152,331 ; D1.2@4125.49,1123 4161,1087.49 4161,780 ; R108.1@4266.5,921 4266.5,990.4 C120.2@4311,1034.91 ; v1(4287,359) 4287,404.5 R111.1@4296,413.5 ; v1(4404.5,234.5) R103.2@4404.5,285 ; v1(4429,1982) C160.1@4374.5,1982 4374.5,2177.5 4397,2200 U38.4@4455.28,2200 ; v1(4477,562) 4441.5,562 C121.2@4426.5,577 4426.5,615 C116.2@4426.5,648 4443.5,665 v1(4477,665) ; v1@4479.5,608 D2.2@4525,608 ; R106.2@4536,439.5 v1(4586.5,439.5)
  Top Layer w30: 406,1033 C67.2@406,1079.5 ; U23.7@505,1058.28 v2(505,1079.94) 505,1178 U22.9@506,1179 ; TP42.1@4118,202 4152,236 C126.2@4152,331
  Top Layer w50: TP53.1@1888.73,1125.92 1888.73,975.92 C94.2@1899.73,964.92
  Bottom Layer w20: R97.1@3170.87,950.84 3170.87,980.87 3181,991 3285.26,991 v2(3285.49,990.77) ; C82.2@3187.49,1110.34 3190.91,1106.91 v2(3285.49,1106.91) ; v1(3214,774.98) 3270.24,774.98 R100.1@3272.49,777.22 ; v1(3293.14,720) C87.2@3330.49,757.35 ; v2(3343.56,1048.84) 3343.56,1142.42 C78.2@3346.98,1145.84 ; C84.2@3460.5,923 3460.5,925.5 v4(3493,958) ; C114.2@4014,817 v1(4014,891)
  Bottom Layer w30: C122.2@4382,816 4382,975 v1(4420,1013)
  other v1: 1022,229 1117,229 1515,394 1595,394 1688,420 1846,420 3710,454 3710,509 3916,549 3173.98,556 3230.98,556 3710,564 3916,599 4477,608 3173.98,613 3230.98,613 3173.98,670 3230.98,670 726,872 791,872 1180,905 1301,906 1422,907 1543,908 620,945 2021,953 2142,954 2263,955 2384,956 321,974 396,974 505,974 4214,1013 2839,1021 2896,1021 4214,1068 4420,1068 2839,1078 2896,1078 4214,1123 4420,1123 4530,1213 4585,1213 1665,1279 1468,1300 4530,1393 4585,1393 3308.61,1433.11 3308.61,1497.11 2571,1523 2344,1528 2571,1587 2344,1592 2628,1929 2677,1929 343,1983 464,1984 585,1985 824,2007 945,2008 463,2105 584,2106 705,2107 826,2108 948,2247 1069,2248 2417,2250 2462,2250 2417,2295 2385,2338 2475,2383 2563,2383 2251,2539 2309,2539 2422,2541 2480,2541
  other v2: 1388.81,331.4 4189.04,585.96 4158.53,615.49 4189.04,615.49 4219.55,615.49 4158.53,656.82 4189.04,656.82 4219.55,656.82 4189.04,686.35 505,1036.63 3227.42,1048.84 506,1157.35 2290.82,1744.52 2342,1744.52 2393.18,1744.52 2290.82,1795.7 2342,1795.7 2393.18,1795.7 2290.82,1850.82 2342,1850.82 2393.18,1850.82 2290.82,1902 2342,1902 2393.18,1902 2290.82,1953.18 2342,1953.18 2393.18,1953.18 1286.14,1993.35 1315.01,1993.35 1343.88,1993.35 1372.76,1993.35 2290.82,2008.3 2342,2008.3 2393.18,2008.3 1286.14,2022.22 1372.76,2022.22 1286.14,2051.09 1372.76,2051.09 2290.82,2059.48 2342,2059.48 2393.18,2059.48 1286.14,2079.96 1315.01,2079.96 1343.88,2079.96 1372.76,2079.96
  other v5: 1511.41,974.24 1511.41,1004.75 1580.31,1020 1565.54,1033.29 1596.06,1033.29 1565.54,1056.91 1596.06,1057.9 1565.54,1080.54 1565.54,1104.16 1565.54,1133.68 1565.54,1157.31 1596.06,1179.94 1565.54,1180.93 1565.54,1204.55 1596.06,1204.55 1580.31,1217.84 1511.41,1233.09 1511.41,1263.61
ILM: R42.2 R43.2 R44.2 TP27.1 U22.7 | length 494.2
  Top Layer w12: U22.7@543.4,1188.84 611.66,1188.84 R42.2@612,1188.5
  Top Layer w15: R42.2@612,1188.5 R43.2@677,1188.5 R44.2@742,1188.5 801.5,1188.5 821,1208 821,1325 846,1350 TP27.1@902,1350
NetC1_1: C1.1 C2.1 C3.2 J2.1 R187.1 TP5.1 U1.27 U1.28 U1.42 U9.4 U9.5 U9.6 | length 114.5
  Top Layer w20: 1682.44,4494.9 U9.4@1682.44,4530.67 U9.5@1682.44,4556.26 U9.6@1682.44,4581.85 1682.44,4609.44
  other v2: 1691.42,3871.13 1725.68,3871.13 1759.14,3871.13 1691.42,3904.6 1759.14,3904.6
  other v3: 1707.67,4233.67 1752.67,4233.67 1797.67,4233.67 1707.67,4278.67 1752.67,4278.67 1797.67,4278.67
NetC7_1: C7.1 C8.1 C12.1 C13.1 R177.1 U2.2 U2.8 U3.2 U3.8 | length 122
  Top Layer w15: v3(2006.74,4555.43) 2024.17,4538 U3.8@2046.5,4538 ; v3(2078,4386.5) U3.2@2078,4421.86 ; v3(2792.26,4382.74) U2.2@2792.26,4421.43
  Bottom Layer w15: v3(2721,4555) v3@2722,4555
  other v1: 1915.74,4651.43 1960.74,4651.43 2630,4651 2675,4651 1915.74,4696.43 1960.74,4696.43 2630,4696 2675,4696
  other v3: 2394,3689 2439,3689 2394,3734 2439,3734 2394,3779 2439,3779
NetC9_2: C9.2 R1.1 R2.2 U2.4 | length 164.9
  Top Layer w10: R2.2@2918.63,4368.57 R2.2@2918.87,4368.8 ; C9.2@2966.01,4422.21 C9.2@2966.07,4422.27
  Top Layer w15: U2.4@2855.25,4421.43 2918.09,4421.43 R1.1@2918.87,4422.21 ; R2.2@2918.87,4368.8 R1.1@2918.87,4422.21 ; C9.2@2966.01,4422.21 R1.1@2918.87,4422.21
NetC14_2: C14.2 R5.1 R6.2 U3.4 | length 202.3
  Top Layer w15: U3.4@2140.99,4421.86 2216.87,4421.86 R5.1@2217.5,4422.5 ; R6.2@2217.5,4356.99 R5.1@2217.5,4422.5 ; C14.2@2277.5,4422.43 2277.44,4422.5 R5.1@2217.5,4422.5
NetC17_1: C17.1 U4.2 | length 305
  Top Layer w10: v4(882,4561) 879.8,4563.2 U4.2@916.94,4563.2 ; v4(892.9,4337.1) C17.1@929.24,4337.1
  Bottom Layer w10: v4(882,4561) 892.9,4550.1 v4(892.9,4337.1)
NetC17_2: C17.2 L2.1 U4.9 | length 190.8
  Top Layer w20: U4.9@991.74,4462.81 991.74,4337.6 C17.2@992.24,4337.1
  Top Layer w40: C17.2@992.24,4337.1 992.24,4272.91 L2.1@992.74,4272.41
NetC18_1: C18.1 C19.1 J1.1 L1.1 U6.4 U6.5 U6.6 | length 102.3
  Top Layer w20: 308.29,4410.77 U6.6@329.82,4410.77 U6.5@355.41,4410.77 U6.4@381,4410.77 410.54,4410.77
  other v1: 385,4496 452,4496 515,4496 385,4559 452,4559 515,4559
NetC20_1: C20.1 C21.1 C22.1 C23.1 L1.2 TP1.1 U4.4 U4.14 U4.15 U4.18 | length 166.5
  Top Layer w10: U4.18@1031.11,4598.64 1031.11,4613.94 1044.17,4627 1083,4627
  Top Layer w20: 1083,4627 1092,4627 v1(1152,4567)
  other v1: 1110,4538 1212,4567 1272,4567 657,4572 716,4572 716,4631 716,4692
NetC26_1: C26.1 RB1.1 U4.22 | length 147.4
  Top Layer w10: RB1.1@841.74,4671.48 890.74,4671.48 952.37,4609.85 U4.22@952.37,4598.64
NetC27_1: C27.1 C110.1 R176.1 U5.1 U5.7 | length 114.2
  Top Layer w10: 188,3778.79 191,3775.79 U5.1@207.57,3775.79 ; C27.1@258.6,3836.26 260.72,3834.14 U5.7@260.72,3769.88 U5.7@286.88,3769.88
NetC28_1: C28.1 C29.1 L3.2 R7.2 R8.2 R118.2 TP3.1 U5.4 U20.1 | length 1078.1
  Top Layer w10: R7.2@145,3670.64 145.31,3670.94 C29.1@207,3670.94 ; C29.1@207.57,3671.51 U5.4@207.57,3716.73 ; 531.34,3698.86 U20.1@552.76,3698.86
  Top Layer w15: R8.2@113.31,3770.26 65.26,3770.26 52,3757 52,3580 72,3560 124,3560 145,3581 ; R7.2@145,3670.64 145,3581 ; 325.08,3560.08 165.92,3560.08 145,3581
  Top Layer w20: L3.2@339.4,3693.69 L3.2@363,3693.69 468.57,3693.69 R118.2@469,3693.26 469,3576.26 TP3.1@463,3570.26 ; R118.2@469.4,3698.86 531.34,3698.86
NetC30_1: C30.1 R9.2 R10.2 U4.21 | length 191.6
  Top Layer w10: C30.1@942.5,4778 955.12,4765.39 R10.2@955.12,4717.1 R9.2@955.12,4668.1 972.05,4651.17 U4.21@972.05,4598.64
NetC33_1: C33.1 U8.5 | length 136.1
  Top Layer w15: C33.1@1121,3618.26 1106,3633.26 1106,3688 1116.87,3698.87 U8.5@1161.68,3698.87
NetC44_1: C44.1 R22.1 R24.2 U11.1 | length 191.4
  Top Layer w10: C44.1@3164.74,4508.24 C44.1@3172.5,4516 3192.84,4536.35 U11.1@3235.75,4536.35
  Top Layer w15: R22.1@3164.74,4399.46 R24.2@3164.74,4449.46 C44.1@3164.74,4508.24
NetC50_1: C50.1 R26.2 R27.2 R28.2 R170.2 U13.4 U13.5 | length 62.5
  Top Layer w15: R28.2@3181.74,3508.62 3182.12,3509 R26.2@3244.12,3509
NetC52_1: C52.1 L17.1 U14.1 U14.3 U14.4 | length 160.2
  Top Layer w15: v3(2807,3828.89) U14.1@2832.39,3803.5
  Bottom Layer w15: v3(2794,3710) 2807,3723 v3(2807,3828.89)
NetC53_1: C53.1 C54.1 L5.1 U13.1 U13.2
NetC55_2: C55.2 U13.8 | length 75.7
  Top Layer w15: U13.8@3269.13,3575.66 3330.9,3575.66 C55.2@3340.74,3585.5
NetC56_1: C56.1 C57.1 L6.1 R167.1
NetC58_1: C58.1 L6.2 U17.3 U17.4 | length 69.4
  Top Layer w10: 4368.15,3868.85 4368.15,3834.11 U17.4@4370,3832.26 ; U17.3@4393.62,3832.26 4395.47,3834.11 4395.47,3863.53
NetC60_1: C60.1 C62.1 TP107.1 U17.6 U17.7 U21.7 | length 115.9
  Top Layer w15: 4370,3673 U17.7@4370,3712.18 ; C62.1@4601.4,3556.71 4617.71,3556.71 4637.41,3576.41 U21.7@4670,3576.41
NetC61_1: C61.1 L7.1 TP18.1 U18.1 U18.3 U18.4 | length 482.7
  Top Layer w15: v1(2539,3396) 2566.11,3396 U18.1@2586.74,3416.63 ; U18.3@2637.92,3416.63 2637.92,3395.08 2702,3331 v1(2753,3331)
  Bottom Layer w15: v1(2539,3396) 2631,3304 2726,3304 v1(2753,3331)
NetC64_1: C64.1 R39.1 R40.2 U21.2 | length 187.4
  Top Layer w12: U21.2@4744.8,3576.41 4763.59,3576.41 4786.17,3553.83 R39.1@4807.4,3553.83
  Top Layer w20: R39.1@4807.4,3553.83 4807.57,3554 R40.2@4857,3554 4857,3608.5 C64.1@4849,3616.5
NetC67_1: C67.1 J5.1 R41.2 R119.2 R179.1 TP22.1 U22.3 U22.4 | length 618.7
  Top Layer w12: C67.1@406,1142.5 432.66,1169.16 U22.3@468.6,1169.16 ; 468,1123 472.93,1127.93 U22.3@472.93,1168.57
  Top Layer w20: TP22.1@561,815 TP22.1@569,823 601.31,790.69 R119.2@601.31,707.48
  Bottom Layer w20: v3(443,1128) 443,949 TP22.1@569,823
  other v3: 219,1144 258,1144 297,1144 219,1183 258,1183 1136,1408 1276,1408 1136,1447 1276,1447
NetC69_1: C69.1 C88.1 C89.1 C90.1 C91.1 R179.2 U24.4 U24.10@1495.66,1045.1 U24.23@1527.16,1068.72 U24.24@1527.16,1169.12 | length 172.5
  Top Layer w20: C90.1@1416.67,1035.42 1418.08,1034 1477.58,1034 1488.68,1045.1 U24.10@1495.66,1045.1 ; C91.1@1416.73,1193.43 1426.31,1203 1487.39,1203 1495.66,1194.73 U24.4@1495.66,1192.74
  other v5: 1511.41,1033.29 1541.92,1033.29 1541.92,1056.91 1511.41,1057.9 1541.92,1080.54 1541.92,1104.16 1541.92,1133.68 1541.92,1157.31 1511.41,1179.94 1541.92,1180.93 1511.41,1204.55 1541.92,1204.55
NetC72_2: C72.2 R80.2 U31.29 | length 259.4
  Top Layer w10: 3258,1194 3275.65,1176.35 U31.29@3275.65,1143.33
  Top Layer w15: v4(3167,1285) 3167.5,1285.5 C72.2@3212,1285.5 3211.5,1285 3211.5,1240.5 3258,1194
  Bottom Layer w15: v4(3167,1285) 3211.5,1285 R80.2@3212,1285.5
NetC74_1: C74.1 C75.1 L13.2 R81.1 R82.2 U31.25 | length 374.9
  Top Layer w10: U31.25@3354.39,1143.33 3406.33,1143.33 3415,1152
  Top Layer w15: L13.2@3428.57,1303.11 3428.95,1302.73 R82.2@3513.49,1302.73
  Top Layer w20: 3415,1152 3424.83,1161.83 ; 3428.57,1165.57 L13.2@3428.57,1303.11
  Top Layer w25: C74.1@3419.98,1433.11 3421.61,1431.49 R81.1@3493.49,1431.49
NetC76_1: C76.1 D11.2 D12.1 D13.1 D14.1 R83.1 | length 436.1
  Top Layer w15: D11.2@2616.21,278.47 2616,278.68 D14.1@2616,367.53 D12.1@2809,367.53
  Top Layer w20: D12.1@2809,367.53 2816.09,374.62 R83.1@2891.53,374.62 C76.1@2891.53,443.13
NetC87_1: C87.1 R98.1 R99.2 U31.14 | length 208.2
  Top Layer w10: U31.14@3315.02,954.35 3315.02,914.98 v4(3320.5,909.5)
  Bottom Layer w15: v4(3320.5,909.5) 3319.11,908.11 R99.2@3319.11,881.84 3319.11,831.72 C87.1@3330.49,820.34 3396.37,820.34 R98.1@3396.87,819.84
NetC100_2: C100.2 J14.1 R52.1 R53.2 U24.15 | length 1128.4
  Top Layer w10: U24.15@1611.8,1079.55 1659.54,1079.55 v4(1691.09,1048) 1693.5,1048 C100.2@1714.5,1027 ; R52.1@2339.23,790.92 R53.2@2404.24,790.92 2405,790.16 v4(2405,752) 2404.73,751.73 J14.1@2404.73,688.92
  Bottom Layer w10: v4(1691.09,1048) 1987.09,752 v4(2405,752)
NetC101_1: C101.1 C102.1 C103.1 C104.1 R180.1 TP28.1 U25.30 U25.31 U25.32 | length 86.1
  Top Layer w20: 1238,1891 1238,1928.48 U25.30@1240.87,1931.34 ; 1308,1891 1315,1898 1315,1928.07 U25.32@1311.73,1931.34
NetC109_2: C109.2 TP31.1 U25.6 | length 210.3
  Top Layer w20: U25.6@1521.38,2144.93 1598.35,2144.93 C109.2@1599.23,2144.05 1599.23,2209.01 TP31.1@1646.72,2256.51
NetC119_1: C119.1 U27.16 | length 108.8
  Top Layer w10: C119.1@4034.5,580 4058.77,580 4105.08,626.32 U27.16@4124.08,626.32
NetC121_1: C121.1 U27.5 | length 129.6
  Top Layer w10: U27.5@4254,626.32 4283.69,626.32 4305,605
  Top Layer w15: 4305.5,605.5 4334,577 C121.1@4363.5,577
NetC123_1: C123.1 U27.19 | length 106.3
  Top Layer w10: C123.1@4099,476.5 4099,551 4115.26,567.26 U27.19@4124.08,567.26
NetC125_2: C125.2 R107.1 R108.2 U27.10 | length 206.4
  Top Layer w10: R107.1@4203.5,796 4218.56,780.94 U27.10@4218.56,720.8
  Top Layer w15: R107.1@4203.5,796 C125.2@4203.5,858 R108.2@4203.5,921
NetC127_1: C127.1 C128.1 J18.1 Q3.1 Q3.2 Q3.3 U28.4
NetC129_1: C129.1 C130.1 C141.1 C142.1 J19.1 Q3.5 Q3.6 Q3.7 Q3.8 Q3.9@913.91,3087.47 Q4.5 Q4.6 Q4.7 Q4.8 Q4.9@3947.43,3229.43 R110.1 R115.1 R154.1 TP41.1 TP95.1 U28.6 U30.6
NetC131_1: C131.1 C132.1 C133.1 R181.2 U29.5 U29.7 U29.8 | length 198.4
  Top Layer w10: 1315.18,361.82 1350.33,361.82 U29.7@1357.31,368.8 1357.31,389.69 1349,398 ; U29.5@1396.68,368.8 1396.68,385.68 v3(1410,399)
  Bottom Layer w20: v3(1325,399) v3(1410,399)
NetC138_2: C138.2 R68.1 R69.2 U29.4 | length 389.3
  Top Layer w12: U29.4@1396.68,294 1396.68,262.32 v4(1399,260)
  Top Layer w15: R69.2@1514,176.62 1522.12,168.5 v4(1560,168.5) 1560,167 1597.62,129.38 R68.1@1600,129.38 C138.2@1649,129.38
  Bottom Layer w15: v4(1399,260) 1490.5,168.5 v4(1560,168.5)
NetC139_1: C139.1 C140.1 J20.2 Q4.1 Q4.2 Q4.3 U30.4
NetC145_1: C145.1 C146.1 U19.11 U19.12 U37.1 U37.2 U37.3
  other v1: 2091.5,1744.5 2037,1745 2037.5,1799.5 1859.5,2033.5 1805,2034 1805.5,2088.5 1860,2088.01
NetC149_1: C149.1 U32.6 | length 107.9
  Top Layer w10: U32.6@4360.91,4574.69 4360.91,4644
  Top Layer w20: C149.1@4360.74,4682.5 4360.91,4682.33 4360.91,4644
NetC149_2: C149.2 L15.1 U32.1 U32.2 U32.3 U32.4 U32.5 | length 66.7
  Top Layer w10: U32.5@4380.6,4574.69 4380.6,4592.29 4408,4619.7 4408,4630
NetC150_1: C150.1 C151.1 R166.1 U32.18 U32.20 U32.21 U32.22 | length 233.4
  Top Layer w10: U32.18@4301.86,4430.99 4301.86,4389.14 4309,4382 4337.24,4382 C151.1@4360.24,4359 ; 4341.23,4396.77 U32.20@4341.23,4430.99 ; C151.1@4365,4351 4380.6,4366.6 U32.22@4380.6,4430.99
NetC152_2: C152.2 U32.7 | length 125.7
  Top Layer w10: C152.2@4298,4682.5 4298,4655.03 4341.23,4611.8 U32.7@4341.23,4574.69
NetC154_2: C154.2 R122.1 R124.2 U32.11 | length 271.1
  Top Layer w10: 4239,4615 4262.49,4591.51 U32.11@4262.49,4574.69
  Top Layer w20: C154.2@4092.74,4682.5 R122.1@4155.74,4682.5 R124.2@4155.74,4614.5 4164.24,4623 4231,4623 4239,4615
NetC161_1: C161.1 R154.2 R158.2 U39.13 U39.14 | length 634.7
  Top Layer w10: U39.13@1977.14,3090.18 1979.86,3087.47 2010.47,3087.47
  Top Layer w20: R158.2@1811.5,2822 v1(1859,2822)
  Bottom Layer w20: v1(1859,2822) 1901,2780 1990,2780 2027,2817 2027,3104 v3(1981,3150)
NetC162_1: C162.1 U39.12 | length 172.6
  Top Layer w12: U39.12@1977.14,3064.59 2047.59,3064.59 2061,3078
  Top Layer w25: 2061,3078 2083.07,3100.07 C162.1@2083.07,3152
NetC162_2: C162.2 L16.1 U39.10 U39.11 | length 164.3
  Top Layer w15: U39.10@1977.14,3013.41 2045.59,3013.41 ; U39.11@1977.14,3039 2073,3039
NetC163_1: C163.1 J4.2 L16.2 R156.2 TP91.1 U39.1 | length 787.7
  Top Layer w12: U39.1@1744.86,3115.77 1748.5,3119.41 R156.2@1748.5,3187
  Top Layer w20: R156.2@1748.5,3187 v1(1748.5,3232.5)
  Bottom Layer w20: v1(1748.5,3232.5) 1968.5,3232.5 2188,3013 v1(2327,3013)
NetC164_2: C164.2 U39.4 | length 110.2
  Top Layer w15: C164.2@1635.09,3040 1636.09,3039 U39.4@1744.86,3039
NetC165_2: C165.2 R157.1 TP92.1 U39.3 | length 652.5
  Top Layer w12: TP92.1@1492,2850.99 1492,2884.5 R157.1@1555.5,2948 1545.5,2958 1478,2958 1464,2972 1464,3074.6 1480,3090.6 1586.1,3090.6 C165.2@1618.5,3123 1647.14,3123 1705.55,3064.59 U39.3@1744.86,3064.59
NetC167_1: C167.1 TP79.1 U40.2 U40.3 | length 258.2
  Top Layer w15: U40.2@3702.13,1902 U40.3@3702.13,1939.4 3760.1,1939.4 C167.1@3772.5,1927 3772.5,2006.5 TP79.1@3819,2053
NetC169_1: C169.1 R164.1 U41.4 | length 154.8
  Top Layer w15: R164.1@3210.56,1914 3213.5,1916.94 C169.1@3213.5,1977 3213.9,1977.4 U41.4@3303.87,1977.4
NetC171_1: C171.1 C172.1 R168.2 TP20.1 U42.1 U42.2
NetC173_1: C173.1 U42.6 | length 107.3
  Top Layer w10: U42.6@4780.35,4358.04 C173.1@4780.35,4465.35
NetC176_1: C176.1 TP99.1 U7.3 U7.8 | length 996.7
  Top Layer w22: U7.8@2358,4620.69 v1(2358,4671) ; TP99.1@2448,4023 2448,4121.14 C176.1@2577.86,4251 2562,4251 v1@2458,4355 ; v1(2457,4356) v1@2458,4355 ; U7.3@2458,4414 v1@2458,4355
  Bottom Layer w22: v1(2358,4671) 2323,4636 2323,4394 2361,4356 v1(2457,4356)
NetC177_1: C177.1 C178.1 J21.2 L11.1
  other v1: 3213,311 3268,311 3213,366 3213,421
NetC182_1: C182.1 TP102.1 U7.4 | length 277.7
  Top Layer w15: U7.4@2508,4414 2578.5,4414 C182.1@2579,4413.5 2640,4352.5 2640,4327 TP102.1@2707,4260
NetC183_2: C183.2 R174.1 R175.2 U10.2 | length 176.7
  Top Layer w10: C183.2@2309,2460.99 2310.5,2459.5 R174.1@2361,2459.5 2362.65,2457.84 U10.2@2484.43,2457.84
NetC184_1: C184.1 R171.2 R172.1 R173.1 U10.7 | length 690.9
  Top Layer w10: U10.7@2537.57,2457.84 2567.84,2457.84 2577.42,2467.42
  Top Layer w15: 2577.42,2467.42 2587,2477 C184.1@2625,2477
  Top Layer w25: C184.1@2625,2477 R171.2@2625,2562 2641.5,2578.5 R173.1@2712,2578.5
  Bottom Layer w15: R172.1@2361.01,2459.5 2361.01,2547.01 2393,2579 v3(2677,2579)
NetC186_1: C186.1 R182.1 R183.2 U16.4
NetC187_1: C187.1 R183.1 U16.1 | length 295.4
  Top Layer w20: v1(685.97,220.33) U16.1@722.57,220.33 ; R183.1@865.97,257.03 875,248 v1(875,200)
  Bottom Layer w20: v1(685.97,220.33) 686.64,221 C187.1@759.97,221 854,221 v1(875,200)
NetC188_1: C188.1 C191.2 L19.2 R184.2 TP109.1 | length 552.6
  Top Layer w20: TP109.1@395,136 395,298 484.53,387.53 R184.2@565.47,387.53 ; C188.1@598.88,135.53 C188.1@598.97,135.44
  Top Layer w30: TP109.1@415.97,135.53 C188.1@598.88,135.53
NetC190_2: C190.2 R186.1 TP110.1 | length 270.6
  Top Layer w20: C190.2@4308.5,2578 4308,2577.5 R186.1@4308,2495.5 4407.5,2495.5 TP110.1@4470,2433
NetC192_1: C192.1 TP111.1 U31.12 | length 757.3
  Top Layer w10: TP111.1@2993,422 2993,668 3045,720 3216,720 3246,750 3246,833 C192.1@3285,872 3285,925 3275.65,934.35 U31.12@3275.65,954.35
NetCVCC1_1: CVCC1.1 U4.1 | length 91.2
  Top Layer w15: CVCC1.1@836.24,4611.1 891.68,4611.1 U4.1@916.94,4585.84
NetD1_1: D1.1 L8.1 Q1.3
NetD2_1: D2.1 L9.1 Q2.3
